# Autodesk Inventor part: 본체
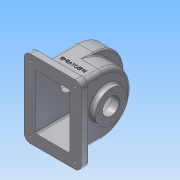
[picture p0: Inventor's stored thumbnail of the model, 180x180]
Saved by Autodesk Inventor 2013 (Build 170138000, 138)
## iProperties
Created: 2017-11
Part Number: 본체
Material: 알루미늄 6061
Document SubType Name: Modeling
Designer: Administrator
Density: 2.71 g/cm^3
Mass: 1079.77 g
Surface Area: 1183.22 cm^2
Volume: 398.438 cm^3
Author: Administrator
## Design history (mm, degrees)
sketch "스케치1"
  geometry: L1 (-80, 58)-(0, 58); L2 (0, 58)-(0, -58); L3 (0, -58)-(-80, -58); L4 (-80, -58)-(-80, 58); A1 r 58 centre (0, 0) between (0, -58) and (0, 58); A2 r 58 centre (-23, 0) between (-23, -58) and (-23, 58); 2 further points
  constraints: 8 end point, 4 point on circle, 3 coincident, 2 centre point, 2 parallel, 2 point on line, 1 horizontal, 1 horizontal alignment, 1 midpoint, 1 perpendicular
  dimensions: "d2" = 116 distance of L1.end L2.end; "d3" = 80 distance of L2.end L3.end; "d7" = 116 diameter of A2; "d8" = 57 distance from line of A2.centre L4
extrude "돌출1" new body sketch "스케치1" distance "d4" = 38; taper "d5" = 0 deg
extrude "돌출2" join sketch "스케치1" distance "d9" = 38; taper "d10" = 0 deg
feature "쉘1" dims "d15" = 5
sketch "스케치2"
  geometry: L1 (-17, 133)-(93, 133); L2 (93, 133)-(93, -17); L3 (93, -17)-(-17, -17); L4 (-17, -17)-(-17, 133); L5 (-17, 133)-(93, -17); L6 (93, 133)-(-17, -17); L7 (0, 116)-(76, 116) reference; L8 (0, 0)-(0, 116) reference; L9 (5, 111)-(71, 111) reference; L10 (71, 111)-(71, 5) reference; L11 (71, 5)-(5, 5) reference; L12 (5, 5)-(5, 111) reference; L13 (0, 116)-(76, 116) reference; L14 (0, 0)-(0, 116) reference; L15 (76, 0)-(0, 0) reference; L16 (76, 116)-(76, 0) reference; 1 further point
  constraints: 12 end point, 2 midpoint, 2 parallel, 1 horizontal, 1 perpendicular
  dimensions: "d11" = 110 distance of L2.end L3.end; "d12" = 150 distance of L1.end L2.end
extrude "돌출3" join sketch "스케치2" distance "d13" = 15; taper "d14" = 0 deg
sketch "스케치3"
  geometry: L1 (-75, -80)-(75, -80) reference; C1 r 37.5 at (0, -15); C2 r 16 at (0, -15); A1 r 58 centre (0, 0) between (58, 0) and (-58, 0) reference
  constraints: 2 centre point, 1 coincident, 1 vertical alignment
  dimensions: "d16" = 75 diameter of C1; "d17" = 32 diameter of C2; "d18" = 65 distance from line of C1.centre L1
extrude "돌출4" join sketch "스케치3" distance "d19" = 9; taper "d20" = 0 deg
extrude "돌출5" cut sketch "스케치3" stored distance "d21" = 0; taper "d22" = 0 deg
sketch "스케치4"
  geometry: C1 r 16 at (0, 0) reference; 5 further points
  constraints: 2 horizontal alignment, 2 vertical alignment
  dimensions: "d23" = 29 distance of point (0, 29) C1.centre; "d24" = 58 distance of point (0, -29) point (0, 29); "d25" = 58 distance of point (29, 0) point (-29, 0); "d26" = 29 distance of C1.centre point (29, 0)
hole "구멍1" sketch "스케치4" at (0, 29), (-29, 0), (0, -29), (29, 0) diameter "d27" = 2.459; stored, may be unused: countersink angle "d31" = 90 deg, drill point angle "d33" = 118 deg; dims "d28" = 6, "d29" = 4, "d30" = 2, "d32" = 8
sketch "스케치5"
  geometry: C1 r 16 at (0, -15) reference; C2 r 31 at (0, -15); 1 further point
  constraints: 1 centre point, 1 coincident
  dimensions: "d35" = 62 diameter of C2
extrude "돌출6" join sketch "스케치5" distance "d36" = 10; taper "d37" = 0 deg
sketch "스케치6" dims "d38" = 52
  geometry: C1 r 16 at (0, 0) reference; C2 r 31 at (0, 0) reference; 3 further points
  constraints: 2 vertical alignment, 1 coincident, 2 other
hole "구멍2" sketch "스케치6" at (0, 26) diameter "d39" = 2.459; stored, may be unused: countersink angle "d43" = 90 deg, drill point angle "d45" = 118 deg; dims "d40" = 6, "d41" = 4, "d42" = 2, "d44" = 8
fillet "모깎기1" dims "d49" = 12, "d50" = 8
fillet "모깎기2" dims "d51" = 3
node "작업 평면1"
sketch "스케치7"
  geometry: C1 r 6 at (19, 0); 1 further point
  constraints: 1 centre point, 1 horizontal alignment
  dimensions: "d52" = 12 diameter of C1; "d53" = 19 distance of point (0, 0) C1.centre
extrude "돌출7" join sketch "스케치7" distance "d54" = 6; taper "d56" = 0 deg; dims "d55" = 5, "d57" = 0
hole "구멍3" diameter "d60" = 4.459; stored, may be unused: countersink angle "d64" = 90 deg, drill point angle "d66" = 118 deg; dims "d58" = 10, "d59" = 10, "d61" = 6, "d62" = 4, "d63" = 2, "d65" = 8
fillet "모깎기3" dims "d67" = 3
fillet "모깎기4" dims "d68" = 3
sketch "스케치8"
  geometry: C1 r 6 at (-5, 5); C2 r 2.5 at (-5, 5); C3 r 6 at (81, 5); C4 r 2.5 at (81, 5); C5 r 6 at (81, -121); C6 r 2.5 at (81, -121); C7 r 6 at (-5, -121); C8 r 2.5 at (-5, -121); A1 r 9 centre (-5, 5) between (-5, 14) and (-14, 5) reference; A2 r 9 centre (-5, -121) between (-14, -121) and (-5, -130) reference; A3 r 9 centre (81, -121) between (81, -130) and (90, -121) reference; A4 r 9 centre (81, 5) between (90, 5) and (81, 14) reference; 1 further point
  constraints: 8 centre point, 8 coincident
  dimensions: "d69" = 12 diameter of C1; "d70" = 5 diameter of C2; "d71" = 12 diameter of C3; "d72" = 5 diameter of C4; "d73" = 12 diameter of C5; "d74" = 5 diameter of C6; "d75" = 12 diameter of C7; "d76" = 5 diameter of C8
extrude "돌출8" cut sketch "스케치8" distance "d77" = 5; taper "d78" = 0 deg
extrude "돌출9" cut sketch "스케치8" stored distance "d79" = 0; taper "d80" = 0 deg
sketch "스케치10"
  geometry: L1 (-13, -18)-(73, -18) reference; L2 (-8, 62)-(-8, 0) reference; 2 further points
  constraints: 1 other
  dimensions: "d85" = 40 distance from line of L1 point (30, 22); "d86" = 38 distance from line of L2 point (30, 22)
feature "엠보싱2" sketch "스케치10" dims "d2" = 116, "d3" = 80, "d7" = 116, "d8" = 57, "d87" = 0.5, "d88" = 0
chamfer "모따기1" distance "d89" = 1; stored, may be unused: second distance "d90" = 2, angle "d91" = 45 deg
node "솔리드1"
pattern_circular "원형 패턴1" dims angle "d47" = 360 deg
node "투영된 루프1"
